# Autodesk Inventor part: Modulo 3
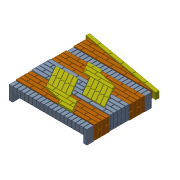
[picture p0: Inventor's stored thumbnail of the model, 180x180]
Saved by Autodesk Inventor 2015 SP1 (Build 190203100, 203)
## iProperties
Created: 2015-04
Part Number: Modulo 3
Material: Generic
Document SubType Name: Modeling
Designer: treina2
Density: 1 g/cm^3
Appearance: Default
Author: treina2
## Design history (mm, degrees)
sketch "Sketch1"
  geometry: L1 (994.875, 828.16)-(1008.247, 805) reference; L2 (1109.875, 329)-(1109.875, 387) reference; L3 (1109.875, 387)-(869.875, 387) reference; L4 (869.875, 387)-(869.875, 329) reference; L5 (340.73, 319)-(244.875, 319) reference; L6 (244.875, 319)-(244.875, 261) reference; L7 (939.842, 183)-(836.807, 183) reference; L8 (939.842, 183)-(744.875, 183) reference; L9 (744.875, 183)-(744.875, 125) reference; L10 (861.322, 319)-(836.807, 319) reference; L11 (739.101, 329)-(859.875, 329) reference; L12 (859.875, 329)-(859.875, 387) reference; L13 (859.875, 387)-(705.615, 387) reference; L14 (1234.875, 941)-(994.875, 941) reference; L15 (994.875, 941)-(994.875, 999) reference; L16 (994.875, 999)-(1234.875, 999) reference; L17 (1234.875, 999)-(1234.875, 941) reference; L18 (619.875, 1134)-(859.875, 1134) reference; L19 (859.875, 1134)-(859.875, 1192) reference; L20 (859.875, 1192)-(619.875, 1192) reference; L21 (619.875, 1192)-(619.875, 1134) reference; L22 (136.5, 0)-(136.5, 115) reference; L23 (136.5, 115)-(194.5, 115) reference; L24 (194.5, 115)-(194.5, 0) reference; L25 (194.5, 0)-(136.5, 0) reference; L26 (859.875, 125)-(973.328, 125) reference; L27 (494.875, 669)-(682.621, 669) reference; L28 (119.875, 465)-(256.437, 465) reference; L29 (301.47, 659)-(234.497, 659) reference; L30 (234.497, 659)-(335.632, 483.83) reference; L31 (335.632, 483.83)-(385.861, 512.83) reference; L32 (385.861, 512.83)-(301.47, 659) reference; L33 (-5.125, 261)-(234.875, 261) reference; L34 (234.875, 261)-(234.875, 319) reference; L35 (234.875, 319)-(-5.125, 319) reference; L36 (-5.125, 319)-(-5.125, 261) reference; L37 (832.83, 329)-(859.875, 329) reference; L38 (859.875, 329)-(859.875, 387) reference; L39 (859.875, 387)-(809.762, 387) reference; L40 (619.875, 193)-(642.243, 193) reference; L41 (340.73, 319)-(244.875, 319) reference; L42 (244.875, 319)-(244.875, 261) reference; L43 (619.875, 197.266)-(619.875, 193) reference; L44 (334.956, 329)-(301.47, 387) reference; L45 (494.875, 261)-(734.875, 261) reference; L46 (244.875, 261)-(369.875, 261) reference; L47 (491.996, 329)-(390.861, 504.17) reference; L48 (744.875, 261)-(849.113, 261) reference; L49 (900.582, 251)-(869.875, 251) reference; L50 (869.875, 251)-(869.875, 193) reference; L51 (385.763, 261)-(352.277, 319) reference; L52 (695.615, 193)-(859.875, 193) reference; L53 (859.875, 193)-(859.875, 251) reference; L54 (859.875, 251)-(619.875, 251) reference; L55 (619.875, 251)-(619.875, 207.447) reference; L56 (945.615, 193)-(1109.875, 193) reference; L57 (1109.875, 193)-(1109.875, 251) reference; L58 (1109.875, 251)-(912.129, 251) reference; L59 (906.355, 261)-(984.875, 261) reference; L60 (984.875, 261)-(984.875, 319) reference; L61 (984.875, 319)-(872.869, 319) reference; L62 (144.431, 659)-(119.875, 659) reference; L63 (119.875, 659)-(119.875, 601) reference; L64 (1234.875, 805)-(1008.247, 805) reference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; 3 further points
  constraints: 1806 end point, 395 horizontal, 258 vertical, 116 point on line, 1005 other
workplane "Work Plane1"
sketch "Sketch2"
  geometry: L1 (0, 1009)-(0, 1124) reference; L2 (0, 1124)-(58, 1124) reference; L3 (58, 1124)-(58, 1009) reference; L4 (58, 1009)-(0, 1009) reference; L5 (0, 0)-(0, 115) reference; L6 (0, 115)-(58, 115) reference; L7 (58, 115)-(58, 0) reference; L8 (58, 0)-(0, 0) reference; L9 (126.25, 1124)-(126.25, 1009) reference; L10 (68.25, 1124)-(126.25, 1124) reference; L11 (68.25, 1009)-(68.25, 1124) reference; L12 (126.25, 1009)-(68.25, 1009) reference; L13 (1354.75, 1124)-(1354.75, 1009) reference; L14 (1296.75, 1124)-(1354.75, 1124) reference; L15 (1296.75, 1009)-(1296.75, 1124) reference; L16 (1354.75, 1009)-(1296.75, 1009) reference; L17 (68.25, 0)-(68.25, 115) reference; L18 (68.25, 115)-(126.25, 115) reference; L19 (126.25, 115)-(126.25, 0) reference; L20 (126.25, 0)-(68.25, 0) reference; L21 (1296.75, 0)-(1296.75, 115) reference; L22 (1296.75, 115)-(1354.75, 115) reference; L23 (1354.75, 115)-(1354.75, 0) reference; L24 (1354.75, 0)-(1296.75, 0) reference; 1 further point
extrude "Extrusion2" new body sketch "Sketch2" distance "d6" = 240; taper "d7" = 0 deg
extrude "Extrusion3" new body sketch "Sketch2" distance "d8" = 240; taper "d9" = 0 deg
extrude "Extrusion4" new body sketch "Sketch2" distance "d10" = 240; taper "d11" = 0 deg
extrude "Extrusion5" new body sketch "Sketch2" distance "d12" = 240; taper "d13" = 0 deg
extrude "Extrusion6" new body sketch "Sketch2" distance "d14" = 115; taper "d15" = 0 deg
extrude "Extrusion7" new body sketch "Sketch2" distance "d16" = 115; taper "d17" = 0 deg
extrude "Extrusion8" new body sketch "Sketch1" distance "d24" = 115; taper "d25" = 0 deg
extrude "Extrusion9" new body sketch "Sketch1" distance "d26" = 240; taper "d27" = 0 deg
extrude "Extrusion10" new body sketch "Sketch1" distance "d28" = 240; taper "d29" = 0 deg
extrude "Extrusion11" new body sketch "Sketch1" distance "d30" = 115; taper "d31" = 0 deg
extrude "Extrusion12" new body sketch "Sketch1" distance "d32" = 115; taper "d33" = 0 deg
extrude "Extrusion13" new body sketch "Sketch1" distance "d34" = 115; taper "d35" = 0 deg
extrude "Extrusion14" new body sketch "Sketch1" distance "d36" = 115; taper "d37" = 0 deg
extrude "Extrusion15" new body sketch "Sketch1" distance "d38" = 115; taper "d39" = 0 deg
extrude "Extrusion16" new body sketch "Sketch1" distance "d40" = 115; taper "d41" = 0 deg
extrude "Extrusion17" new body sketch "Sketch1" distance "d42" = 115; taper "d43" = 0 deg
extrude "Extrusion18" new body sketch "Sketch1" distance "d44" = 115; taper "d45" = 0 deg
extrude "Extrusion19" new body sketch "Sketch1" distance "d46" = 115; taper "d47" = 0 deg
extrude "Extrusion20" new body sketch "Sketch1" distance "d48" = 115; taper "d49" = 0 deg
extrude "Extrusion21" new body sketch "Sketch1" distance "d50" = 115; taper "d51" = 0 deg
extrude "Extrusion22" new body sketch "Sketch1" distance "d52" = 115; taper "d53" = 0 deg
extrude "Extrusion23" new body sketch "Sketch1" distance "d54" = 115; taper "d55" = 0 deg
extrude "Extrusion24" new body sketch "Sketch1" distance "d56" = 115; taper "d57" = 0 deg
extrude "Extrusion25" new body sketch "Sketch1" distance "d58" = 115; taper "d59" = 0 deg
extrude "Extrusion26" new body sketch "Sketch1" distance "d60" = 115; taper "d61" = 0 deg
extrude "Extrusion27" new body sketch "Sketch1" distance "d62" = 115; taper "d63" = 0 deg
extrude "Extrusion28" new body sketch "Sketch1" distance "d64" = 115; taper "d65" = 0 deg
extrude "Extrusion29" new body sketch "Sketch1" distance "d66" = 115; taper "d67" = 0 deg
extrude "Extrusion30" new body sketch "Sketch1" distance "d68" = 115; taper "d69" = 0 deg
extrude "Extrusion31" new body sketch "Sketch1" distance "d70" = 115; taper "d71" = 0 deg
extrude "Extrusion32" new body sketch "Sketch1" distance "d72" = 115; taper "d73" = 0 deg
extrude "Extrusion33" new body sketch "Sketch1" distance "d74" = 115; taper "d75" = 0 deg
extrude "Extrusion34" new body sketch "Sketch1" distance "d76" = 115; taper "d77" = 0 deg
extrude "Extrusion35" new body sketch "Sketch1" distance "d78" = 115; taper "d79" = 0 deg
extrude "Extrusion36" new body sketch "Sketch1" distance "d80" = 115; taper "d81" = 0 deg
extrude "Extrusion37" new body sketch "Sketch1" distance "d82" = 240; taper "d83" = 0 deg
extrude "Extrusion38" new body sketch "Sketch1" distance "d84" = 240; taper "d85" = 0 deg
extrude "Extrusion39" new body sketch "Sketch1" distance "d86" = 240; taper "d87" = 0 deg
extrude "Extrusion40" new body sketch "Sketch1" distance "d88" = 240; taper "d89" = 0 deg
extrude "Extrusion41" new body sketch "Sketch1" distance "d90" = 115; taper "d91" = 0 deg
extrude "Extrusion42" new body sketch "Sketch1" distance "d92" = 115; taper "d93" = 0 deg
extrude "Extrusion43" new body sketch "Sketch1" distance "d94" = 115; taper "d95" = 0 deg
extrude "Extrusion44" new body sketch "Sketch1" distance "d96" = 115; taper "d97" = 0 deg
extrude "Extrusion45" new body sketch "Sketch1" distance "d98" = 115; taper "d99" = 0 deg
extrude "Extrusion46" new body sketch "Sketch1" distance "d100" = 115; taper "d101" = 0 deg
extrude "Extrusion47" new body sketch "Sketch1" distance "d102" = 115; taper "d103" = 0 deg
extrude "Extrusion48" new body sketch "Sketch1" distance "d104" = 115; taper "d105" = 0 deg
extrude "Extrusion49" new body sketch "Sketch1" distance "d106" = 115; taper "d107" = 0 deg
extrude "Extrusion50" new body sketch "Sketch1" distance "d108" = 115; taper "d109" = 0 deg
extrude "Extrusion51" new body sketch "Sketch1" distance "d110" = 115; taper "d111" = 0 deg
extrude "Extrusion52" new body sketch "Sketch1" distance "d112" = 115; taper "d113" = 0 deg
extrude "Extrusion53" new body sketch "Sketch1" distance "d114" = 240; taper "d115" = 0 deg
extrude "Extrusion54" new body sketch "Sketch1" distance "d116" = 240; taper "d117" = 0 deg
extrude "Extrusion68" new body sketch "Sketch1" distance "d144" = 240; taper "d145" = 0 deg
extrude "Extrusion69" new body sketch "Sketch1" distance "d146" = 240; taper "d147" = 0 deg
extrude "Extrusion70" new body sketch "Sketch1" distance "d148" = 115; taper "d149" = 0 deg
extrude "Extrusion71" new body sketch "Sketch1" distance "d150" = 115; taper "d151" = 0 deg
extrude "Extrusion72" new body sketch "Sketch1" distance "d152" = 115; taper "d153" = 0 deg
extrude "Extrusion73" new body sketch "Sketch1" distance "d154" = 115; taper "d155" = 0 deg
extrude "Extrusion74" new body sketch "Sketch1" distance "d156" = 115; taper "d157" = 0 deg
extrude "Extrusion75" new body sketch "Sketch1" distance "d158" = 115; taper "d159" = 0 deg
extrude "Extrusion76" new body sketch "Sketch1" distance "d160" = 115; taper "d161" = 0 deg
extrude "Extrusion77" new body sketch "Sketch1" distance "d162" = 115; taper "d163" = 0 deg
extrude "Extrusion78" new body sketch "Sketch1" distance "d164" = 115; taper "d165" = 0 deg
extrude "Extrusion79" new body sketch "Sketch1" distance "d166" = 115; taper "d167" = 0 deg
workplane "Work Plane2"
sketch "Sketch3"
  geometry: L1 (-5.125, 669)-(234.875, 669) reference; L2 (234.875, 727)-(-5.125, 727) reference; L3 (-5.125, 727)-(-5.125, 669) reference; L4 (234.875, 669)-(234.875, 727) reference; L5 (244.875, 727)-(244.875, 669) reference; L6 (392.943, 727)-(244.875, 727) reference; L7 (244.875, 669)-(369.875, 669) reference; L8 (380.637, 669)-(682.621, 669) reference; L9 (484.875, 727)-(244.875, 727) reference; L10 (484.875, 669)-(484.875, 727) reference; L11 (494.875, 727)-(494.875, 669) reference; L12 (649.135, 727)-(494.875, 727) reference; L13 (244.875, 669)-(484.875, 669) reference; L14 (682.621, 669)-(649.135, 727) reference; L15 (582.062, 601)-(609.875, 601) reference; L16 (609.875, 601)-(609.875, 659) reference; L17 (609.875, 659)-(548.576, 659) reference; L18 (548.576, 659)-(582.062, 601) reference; L19 (619.875, 659)-(619.875, 601) reference; L20 (688.395, 659)-(619.875, 659) reference; L21 (721.881, 601)-(688.395, 659) reference; L22 (619.875, 601)-(721.881, 601) reference; L23 (727.654, 591)-(587.836, 591) reference; L24 (734.875, 578.494)-(727.654, 591) reference; L25 (734.875, 533)-(734.875, 578.494) reference; L26 (621.322, 533)-(734.875, 533) reference; L27 (621.322, 533)-(587.836, 591) reference; L28 (660.582, 465)-(627.096, 523) reference; L29 (766.914, 523)-(627.096, 523) reference; L30 (800.401, 465)-(766.914, 523) reference; L31 (660.582, 465)-(800.401, 465) reference; L32 (744.875, 533)-(761.141, 533) reference; L33 (744.875, 561.173)-(744.875, 533) reference; L34 (761.141, 533)-(744.875, 561.173) reference; L35 (699.842, 397)-(734.875, 397) reference; L36 (734.875, 397)-(734.875, 455) reference; L37 (699.842, 397)-(666.355, 455) reference; L38 (734.875, 455)-(666.355, 455) reference; L39 (744.875, 455)-(744.875, 397) reference; L40 (984.875, 455)-(744.875, 455) reference; L41 (744.875, 397)-(849.113, 397) reference; L42 (859.875, 397)-(984.875, 397) reference; L43 (984.875, 397)-(984.875, 455) reference; L44 (744.875, 397)-(984.875, 397) reference; L45 (994.875, 455)-(1234.875, 455) reference; L46 (994.875, 397)-(994.875, 455) reference; L47 (1234.875, 397)-(994.875, 397) reference; L48 (1234.875, 455)-(1234.875, 397) reference; L49 (1359.875, 455)-(1244.875, 455) reference; L50 (1244.875, 455)-(1244.875, 397) reference; L51 (1244.875, 397)-(1359.875, 397) reference; L52 (1359.875, 397)-(1359.875, 455) reference; L53 (1359.875, 465)-(1204.546, 465) reference; L54 (1359.875, 523)-(1359.875, 465) reference; L55 (1171.059, 523)-(1359.875, 523) reference; L56 (1171.059, 523)-(1204.546, 465) reference; L57 (1234.875, 533)-(1165.286, 533) reference; L58 (1234.875, 591)-(1234.875, 533) reference; L59 (1131.8, 591)-(1234.875, 591) reference; L60 (1131.8, 591)-(1165.286, 533) reference; L61 (1359.875, 601)-(1126.026, 601) reference; L62 (1119.875, 611.654)-(1126.026, 601) reference; L63 (1119.875, 611.654)-(1119.875, 659) reference; L64 (1109.875, 628.975)-(1109.875, 659) reference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; 1 further point
extrude "Extrusion80" new body sketch "Sketch3" distance "d169" = 115; taper "d170" = 0 deg
extrude "Extrusion81" new body sketch "Sketch3" distance "d171" = 115; taper "d172" = 0 deg
extrude "Extrusion82" new body sketch "Sketch3" distance "d173" = 115; taper "d174" = 0 deg
extrude "Extrusion83" new body sketch "Sketch3" distance "d175" = 115; taper "d176" = 0 deg
extrude "Extrusion84" new body sketch "Sketch3" distance "d177" = 115; taper "d178" = 0 deg
extrude "Extrusion85" new body sketch "Sketch3" distance "d179" = 115; taper "d180" = 0 deg
extrude "Extrusion86" new body sketch "Sketch3" distance "d181" = 115; taper "d182" = 0 deg
extrude "Extrusion87" new body sketch "Sketch3" distance "d183" = 115; taper "d184" = 0 deg
extrude "Extrusion88" new body sketch "Sketch3" distance "d185" = 115; taper "d186" = 0 deg
extrude "Extrusion89" new body sketch "Sketch3" distance "d187" = 115; taper "d188" = 0 deg
extrude "Extrusion90" new body sketch "Sketch3" distance "d189" = 115; taper "d190" = 0 deg
extrude "Extrusion91" new body sketch "Sketch3" distance "d191" = 115; taper "d192" = 0 deg
extrude "Extrusion92" new body sketch "Sketch3" distance "d193" = 115; taper "d194" = 0 deg
extrude "Extrusion93" new body sketch "Sketch3" distance "d195" = 115; taper "d196" = 0 deg
extrude "Extrusion94" new body sketch "Sketch3" distance "d197" = 115; taper "d198" = 0 deg
extrude "Extrusion95" new body sketch "Sketch3" distance "d199" = 115; taper "d200" = 0 deg
extrude "Extrusion96" new body sketch "Sketch3" distance "d201" = 115; taper "d202" = 0 deg
extrude "Extrusion97" new body sketch "Sketch3" distance "d203" = 115; taper "d204" = 0 deg
extrude "Extrusion98" new body sketch "Sketch3" distance "d205" = 115; taper "d206" = 0 deg
extrude "Extrusion99" new body sketch "Sketch3" distance "d207" = 115; taper "d208" = 0 deg
extrude "Extrusion100" new body sketch "Sketch3" distance "d209" = 115; taper "d210" = 0 deg
extrude "Extrusion101" new body sketch "Sketch3" distance "d211" = 240; taper "d212" = 0 deg
extrude "Extrusion102" new body sketch "Sketch3" distance "d213" = 240; taper "d214" = 0 deg
extrude "Extrusion103" new body sketch "Sketch3" distance "d215" = 240; taper "d216" = 0 deg
extrude "Extrusion104" new body sketch "Sketch3" distance "d217" = 240; taper "d218" = 0 deg
extrude "Extrusion105" new body sketch "Sketch3" distance "d219" = 240; taper "d220" = 0 deg
workplane "Work Plane3"
sketch "Sketch4"
  geometry: L1 (-46.235, 1450.984)-(190.119, 1409.309) reference; L2 (190.119, 1409.309)-(180.047, 1352.19) reference; L3 (-56.307, 1393.865)-(-46.235, 1450.984) reference; L4 (180.047, 1352.19)-(-56.307, 1393.865) reference; L5 (199.967, 1407.572)-(436.321, 1365.897) reference; L6 (189.895, 1350.453)-(199.967, 1407.572) reference; L7 (436.321, 1365.897)-(426.249, 1308.778) reference; L8 (436.097, 1307.041)-(446.169, 1364.16) reference; L9 (446.169, 1364.16)-(682.523, 1322.485) reference; L10 (682.299, 1263.629)-(692.371, 1320.748) reference; L11 (692.371, 1320.748)-(928.724, 1279.072) reference; L12 (682.523, 1322.485)-(672.451, 1265.366) reference; L13 (928.501, 1220.217)-(938.573, 1277.336) reference; L14 (928.724, 1279.072)-(918.653, 1221.954) reference; L15 (938.573, 1277.336)-(1174.926, 1235.66) reference; L16 (1174.703, 1176.805)-(1184.775, 1233.924) reference; L17 (1174.926, 1235.66)-(1164.855, 1178.542) reference; L18 (1184.775, 1233.924)-(1421.128, 1192.248) reference; L19 (1411.057, 1135.13)-(1174.703, 1176.805) reference; L20 (1421.128, 1192.248)-(1411.057, 1135.13) reference; 3 further points
  constraints: 1 other
extrude "Extrusion106" new body sketch "Sketch4" distance "d222" = 115; taper "d223" = 0 deg
extrude "Extrusion107" new body sketch "Sketch4" distance "d224" = 115; taper "d225" = 0 deg
extrude "Extrusion108" new body sketch "Sketch4" distance "d226" = 115; taper "d227" = 0 deg
extrude "Extrusion109" new body sketch "Sketch4" distance "d228" = 115; taper "d229" = 0 deg
extrude "Extrusion110" new body sketch "Sketch4" distance "d230" = 115; taper "d231" = 0 deg
extrude "Extrusion111" new body sketch "Sketch4" distance "d232" = 115; taper "d233" = 0 deg
workplane "Work Plane4"
sketch "Sketch5"
  geometry: L1 (994.875, 828.16)-(1008.247, 805) reference; L2 (1109.875, 329)-(1109.875, 387) reference; L3 (1109.875, 387)-(869.875, 387) reference; L4 (869.875, 387)-(869.875, 329) reference; L5 (340.73, 319)-(244.875, 319) reference; L6 (244.875, 319)-(244.875, 261) reference; L7 (939.842, 183)-(836.807, 183) reference; L8 (939.842, 183)-(744.875, 183) reference; L9 (744.875, 183)-(744.875, 125) reference; L10 (861.322, 319)-(836.807, 319) reference; L11 (739.101, 329)-(859.875, 329) reference; L12 (859.875, 329)-(859.875, 387) reference; L13 (859.875, 387)-(705.615, 387) reference; L14 (1234.875, 941)-(994.875, 941) reference; L15 (994.875, 941)-(994.875, 999) reference; L16 (994.875, 999)-(1234.875, 999) reference; L17 (1234.875, 999)-(1234.875, 941) reference; L18 (619.875, 1134)-(859.875, 1134) reference; L19 (859.875, 1134)-(859.875, 1192) reference; L20 (859.875, 1192)-(619.875, 1192) reference; L21 (619.875, 1192)-(619.875, 1134) reference; L22 (136.5, 0)-(136.5, 115) reference; L23 (136.5, 115)-(194.5, 115) reference; L24 (194.5, 115)-(194.5, 0) reference; L25 (194.5, 0)-(136.5, 0) reference; L26 (859.875, 125)-(973.328, 125) reference; L27 (494.875, 669)-(682.621, 669) reference; L28 (119.875, 465)-(256.437, 465) reference; L29 (301.47, 659)-(234.497, 659) reference; L30 (234.497, 659)-(335.632, 483.83) reference; L31 (335.632, 483.83)-(385.861, 512.83) reference; L32 (385.861, 512.83)-(301.47, 659) reference; L33 (-5.125, 261)-(234.875, 261) reference; L34 (234.875, 261)-(234.875, 319) reference; L35 (234.875, 319)-(-5.125, 319) reference; L36 (-5.125, 319)-(-5.125, 261) reference; L37 (832.83, 329)-(859.875, 329) reference; L38 (859.875, 329)-(859.875, 387) reference; L39 (859.875, 387)-(809.762, 387) reference; L40 (619.875, 193)-(642.243, 193) reference; L41 (340.73, 319)-(244.875, 319) reference; L42 (244.875, 319)-(244.875, 261) reference; L43 (619.875, 197.266)-(619.875, 193) reference; L44 (334.956, 329)-(301.47, 387) reference; L45 (494.875, 261)-(734.875, 261) reference; L46 (244.875, 261)-(369.875, 261) reference; L47 (491.996, 329)-(390.861, 504.17) reference; L48 (744.875, 261)-(849.113, 261) reference; L49 (900.582, 251)-(869.875, 251) reference; L50 (869.875, 251)-(869.875, 193) reference; L51 (385.763, 261)-(352.277, 319) reference; L52 (695.615, 193)-(859.875, 193) reference; L53 (859.875, 193)-(859.875, 251) reference; L54 (859.875, 251)-(619.875, 251) reference; L55 (619.875, 251)-(619.875, 207.447) reference; L56 (945.615, 193)-(1109.875, 193) reference; L57 (1109.875, 193)-(1109.875, 251) reference; L58 (1109.875, 251)-(912.129, 251) reference; L59 (906.355, 261)-(984.875, 261) reference; L60 (984.875, 261)-(984.875, 319) reference; L61 (984.875, 319)-(872.869, 319) reference; L62 (144.431, 659)-(119.875, 659) reference; L63 (119.875, 659)-(119.875, 601) reference; L64 (1234.875, 805)-(1008.247, 805) reference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; 4 further points
  constraints: 1806 end point, 395 horizontal, 258 vertical, 116 point on line, 1005 other
extrude "Extrusion112" new body sketch "Sketch5" distance "d235" = 115; taper "d236" = 0 deg
extrude "Extrusion113" new body sketch "Sketch5" distance "d237" = 115; taper "d238" = 0 deg
extrude "Extrusion114" new body sketch "Sketch5" distance "d239" = 115; taper "d240" = 0 deg
extrude "Extrusion115" new body sketch "Sketch5" distance "d241" = 115; taper "d242" = 0 deg
extrude "Extrusion116" new body sketch "Sketch5" distance "d243" = 115; taper "d244" = 0 deg
extrude "Extrusion117" new body sketch "Sketch5" distance "d245" = 115; taper "d246" = 0 deg
extrude "Extrusion118" new body sketch "Sketch5" distance "d247" = 115; taper "d248" = 0 deg
extrude "Extrusion119" new body sketch "Sketch5" distance "d249" = 115; taper "d250" = 0 deg
extrude "Extrusion120" new body sketch "Sketch5" distance "d251" = 115; taper "d252" = 0 deg
extrude "Extrusion121" new body sketch "Sketch5" distance "d253" = 115; taper "d254" = 0 deg
extrude "Extrusion122" new body sketch "Sketch5" distance "d255" = 115; taper "d256" = 0 deg
extrude "Extrusion123" new body sketch "Sketch5" distance "d257" = 115; taper "d258" = 0 deg
extrude "Extrusion124" new body sketch "Sketch5" distance "d259" = 115; taper "d260" = 0 deg
extrude "Extrusion125" new body sketch "Sketch5" distance "d261" = 115; taper "d262" = 0 deg
extrude "Extrusion126" new body sketch "Sketch5" distance "d263" = 115; taper "d264" = 0 deg
extrude "Extrusion127" new body sketch "Sketch5" distance "d265" = 115; taper "d266" = 0 deg
extrude "Extrusion128" new body sketch "Sketch5" distance "d267" = 115; taper "d268" = 0 deg
extrude "Extrusion129" new body sketch "Sketch5" distance "d269" = 115; taper "d270" = 0 deg
extrude "Extrusion130" new body sketch "Sketch5" distance "d271" = 115; taper "d272" = 0 deg
extrude "Extrusion131" new body sketch "Sketch5" distance "d273" = 115; taper "d274" = 0 deg
extrude "Extrusion132" new body sketch "Sketch5" distance "d275" = 115; taper "d276" = 0 deg
extrude "Extrusion133" new body sketch "Sketch5" distance "d277" = 115; taper "d278" = 0 deg
extrude "Extrusion134" new body sketch "Sketch5" distance "d279" = 115; taper "d280" = 0 deg
extrude "Extrusion135" new body sketch "Sketch5" distance "d281" = 115; taper "d282" = 0 deg
extrude "Extrusion136" new body sketch "Sketch5" distance "d283" = 115; taper "d284" = 0 deg
extrude "Extrusion137" new body sketch "Sketch5" distance "d285" = 115; taper "d286" = 0 deg
extrude "Extrusion138" new body sketch "Sketch5" distance "d287" = 115; taper "d288" = 0 deg
extrude "Extrusion139" new body sketch "Sketch5" distance "d289" = 115; taper "d290" = 0 deg
extrude "Extrusion140" new body sketch "Sketch5" distance "d291" = 115; taper "d292" = 0 deg
extrude "Extrusion141" new body sketch "Sketch5" distance "d293" = 115; taper "d294" = 0 deg
extrude "Extrusion142" new body sketch "Sketch5" distance "d295" = 115; taper "d296" = 0 deg
extrude "Extrusion143" new body sketch "Sketch5" distance "d297" = 115; taper "d298" = 0 deg
extrude "Extrusion144" new body sketch "Sketch5" distance "d299" = 115; taper "d300" = 0 deg
extrude "Extrusion145" new body sketch "Sketch5" distance "d301" = 115; taper "d302" = 0 deg
extrude "Extrusion146" new body sketch "Sketch5" distance "d303" = 115; taper "d304" = 0 deg
extrude "Extrusion147" new body sketch "Sketch5" distance "d305" = 115; taper "d306" = 0 deg
workplane "Work Plane5"
sketch "Sketch6"
  geometry: L1 (-1119.875, 931)-(-1359.875, 931) reference; L2 (-1359.875, 873)-(-1244.875, 873); L3 (-1244.875, 873)-(-1244.875, 931); L4 (-1244.875, 931)-(-1359.875, 931); L5 (-1359.875, 931)-(-1359.875, 873); 1 further point
  constraints: 8 end point, 2 parallel, 1 horizontal, 1 perpendicular, 1 point on line
  dimensions: "d308" = 115 distance between parallel lines of L5 L3
extrude "Extrusion148" new body sketch "Sketch6" stored distance "d309" = 115; taper "d310" = 0 deg
pattern_linear "Rectangular Pattern5" dims "d316" = 136
workplane "Work Plane6"
sketch "Sketch7"
  geometry: L1 (-1119.875, 659)-(-1359.875, 659) reference; L2 (-1359.875, 601)-(-1244.875, 601); L3 (-1244.875, 601)-(-1244.875, 659); L4 (-1244.875, 659)-(-1359.875, 659); L5 (-1359.875, 659)-(-1359.875, 601); 1 further point
  constraints: 8 end point, 2 parallel, 1 horizontal, 1 perpendicular, 1 point on line
  dimensions: "d318" = 115 distance between parallel lines of L5 L3
extrude "Extrusion149" new body sketch "Sketch7" distance "d319" = 115; taper "d320" = 0 deg
pattern_linear "Rectangular Pattern6" dims "d323" = 136
workplane "Work Plane7"
sketch "Sketch8"
  geometry: L1 (-1119.875, 387)-(-1359.875, 387) reference; L2 (-1359.875, 329)-(-1244.875, 329); L3 (-1244.875, 329)-(-1244.875, 387); L4 (-1244.875, 387)-(-1359.875, 387); L5 (-1359.875, 387)-(-1359.875, 329); 1 further point
  constraints: 8 end point, 2 parallel, 1 horizontal, 1 perpendicular, 1 point on line
  dimensions: "d325" = 115 distance between parallel lines of L5 L3
extrude "Extrusion150" new body sketch "Sketch8" distance "d326" = 115; taper "d327" = 0 deg
pattern_linear "Rectangular Pattern7" dims "d330" = 136
workplane "Work Plane8"
sketch "Sketch9"
  geometry: L1 (-234.875, 1202)-(5.125, 1202) reference; L2 (5.125, 1260)-(-109.875, 1260); L3 (-109.875, 1260)-(-109.875, 1202); L4 (-109.875, 1202)-(5.125, 1202); L5 (5.125, 1202)-(5.125, 1260); 1 further point
  constraints: 8 end point, 2 parallel, 1 horizontal, 1 perpendicular, 1 point on line
  dimensions: "d332" = 115 distance between parallel lines of L5 L3
extrude "Extrusion151" new body sketch "Sketch9" distance "d333" = 115; taper "d334" = 0 deg
workplane "Work Plane9"
sketch "Sketch10"
  geometry: L1 (-234.875, 941)-(5.125, 941) reference; L2 (5.125, 999)-(-109.875, 999); L3 (-109.875, 999)-(-109.875, 941); L4 (-109.875, 941)-(5.125, 941); L5 (5.125, 941)-(5.125, 999); 1 further point
  constraints: 8 end point, 2 parallel, 1 horizontal, 1 perpendicular, 1 point on line
  dimensions: "d336" = 115 distance between parallel lines of L5 L3
extrude "Extrusion152" new body sketch "Sketch10" distance "d337" = 115; taper "d338" = 0 deg
pattern_linear "Rectangular Pattern8" dims "d341" = 136
workplane "Work Plane10"
sketch "Sketch11"
  geometry: L1 (-234.875, 669)-(5.125, 669) reference; L2 (5.125, 727)-(-109.875, 727); L3 (-109.875, 727)-(-109.875, 669); L4 (-109.875, 669)-(5.125, 669); L5 (5.125, 669)-(5.125, 727); 1 further point
  constraints: 8 end point, 2 parallel, 1 horizontal, 1 perpendicular, 1 point on line
  dimensions: "d343" = 115 distance between parallel lines of L5 L3
extrude "Extrusion153" new body sketch "Sketch11" distance "d344" = 115; taper "d345" = 0 deg
pattern_linear "Rectangular Pattern9" dims "d348" = 136
workplane "Work Plane11"
sketch "Sketch12"
  geometry: L1 (5.125, 319)-(-109.875, 319); L2 (-109.875, 319)-(-109.875, 261); L3 (-109.875, 261)-(5.125, 261); L4 (5.125, 261)-(5.125, 319); 1 further point
  constraints: 8 end point, 2 parallel, 1 horizontal, 1 perpendicular
  dimensions: "d350" = 115 distance between parallel lines of L4 L2
extrude "Extrusion154" new body sketch "Sketch12" distance "d351" = 115; taper "d352" = 0 deg
pattern_linear "Rectangular Pattern10" dims "d355" = 136
workplane "Work Plane12"
sketch "Sketch14"
  geometry: L1 (-109.875, 1338)-(-109.875, 1354.409); L2 (5.125, 1338)-(-109.875, 1338); L3 (-202.934, 1338)-(5.125, 1338) reference; L4 (5.125, 1374.686)-(-109.875, 1354.409); L5 (5.125, 1374.686)-(-202.934, 1338) reference; L6 (5.125, 1338)-(5.125, 1374.686); L7 (5.125, 1338)-(5.125, 1374.686) reference; 2 further points
  constraints: 8 end point, 2 point on line, 1 collinear, 1 vertical
extrude "Extrusion155" new body sketch "Sketch14" distance "d357" = 115; taper "d358" = 0 deg
workplane "Work Plane13"
sketch "Sketch15"
  geometry: L1 (621.422, 795)-(811.948, 465); L2 (722.556, 619.83)-(621.422, 795) reference; L3 (811.948, 465)-(1192.999, 465); L4 (1192.999, 465)-(1126.026, 465) reference; L5 (1192.999, 465)-(957.44, 873); L6 (957.44, 873)-(653.361, 931); L7 (653.361, 931)-(859.875, 891.61) reference; L8 (653.361, 931)-(614.101, 999); L9 (614.101, 999)-(375.649, 999); L10 (375.649, 999)-(484.875, 999) reference; L11 (375.649, 999)-(487.654, 805); L12 (409.135, 941)-(375.649, 999) reference; L13 (621.422, 795)-(615.649, 805); L14 (734.875, 805)-(494.875, 805) reference; L15 (615.649, 805)-(487.654, 805); L16 (646.99, 922.035)-(951.069, 864.035); L17 (951.069, 864.035)-(1175.678, 475); L18 (1175.678, 475)-(817.721, 475); L19 (817.721, 475)-(630.082, 800); L20 (630.082, 800)-(621.422, 815); L21 (621.422, 815)-(493.428, 815); L22 (493.428, 815)-(392.969, 989); L23 (392.969, 989)-(608.328, 989); L24 (608.328, 989)-(646.99, 922.035); L25 (155.978, 659)-(537.029, 659); L26 (537.029, 659)-(733.328, 319); L27 (626.42, 504.17)-(727.554, 329) reference; L28 (733.328, 319)-(859.875, 319); L29 (859.875, 319)-(971.881, 125); L30 (971.881, 125)-(734.615, 125); L31 (973.328, 125)-(744.875, 125) reference; L32 (734.615, 125)-(695.323, 193.056); L33 (695.323, 193.056)-(391.537, 251); L34 (609.875, 209.354)-(391.537, 251) reference; L35 (391.537, 251)-(155.978, 659); L36 (531.255, 649)-(173.298, 649); L37 (173.298, 649)-(397.908, 259.965); L38 (397.908, 259.965)-(701.694, 202.021); L39 (701.694, 202.021)-(740.388, 135); L40 (740.388, 135)-(954.56, 135); L41 (954.56, 135)-(854.101, 309); L42 (854.101, 309)-(727.554, 309); L43 (727.554, 309)-(531.255, 649); 1 further point
  constraints: 68 end point, 12 parallel, 8 collinear, 1 horizontal, 1 point on line, 15 other
  dimensions: "d360" = 10 distance between parallel lines of L6 L16; "d361" = 10 distance between parallel lines of L25 L36
extrude "Extrusion156" new body sketch "Sketch15" distance "d362" = 95; taper "d363" = 0 deg
workplane "Work Plane14"
sketch "Sketch16"
  geometry: L1 (646.99, 922.035)-(951.069, 864.035) reference; L2 (608.328, 989)-(646.99, 922.035) reference; L3 (392.969, 989)-(608.328, 989) reference; L4 (493.428, 815)-(392.969, 989) reference; L5 (621.422, 815)-(493.428, 815) reference; L6 (817.721, 475)-(621.422, 815) reference; L7 (1175.678, 475)-(817.721, 475) reference; L8 (951.069, 864.035)-(1175.678, 475) reference; L9 (531.255, 649)-(173.298, 649) reference; L10 (173.298, 649)-(397.908, 259.965) reference; L11 (397.908, 259.965)-(701.694, 202.021) reference; L12 (701.694, 202.021)-(740.388, 135) reference; L13 (740.388, 135)-(954.56, 135) reference; L14 (954.56, 135)-(854.101, 309) reference; L15 (854.101, 309)-(727.554, 309) reference; L16 (727.554, 309)-(531.255, 649) reference; L17 (1354.75, 0)-(1296.75, 0) reference; L18 (1344.75, 0)-(10, 0); L19 (58, 0)-(0, 0) reference; L20 (1344.75, 0)-(1344.75, 1195.562); L21 (10, 0)-(10, 1430.914); L22 (-46.235, 1450.984)-(190.119, 1409.309) reference; L23 (1184.775, 1233.924)-(1421.128, 1192.248) reference; L24 (10, 1430.914)-(1344.75, 1195.562); 2 further points
  constraints: 8 end point, 4 point on line, 2 vertical, 1 parallel
  dimensions: "d367" = 10 distance from line of L17.start L20; "d368" = 10 distance from line of L19.end L21 (= d367); "d370" = 10 distance between parallel lines of L24 L22
extrude "Extrusion157" join sketch "Sketch16" distance "d365" = 95; taper "d366" = 0 deg
sketch "Sketch17"
  geometry: L1 (1490.517, 397)-(1490.517, -135.871); L2 (1490.517, -135.871)-(-86.242, -135.871); L3 (-86.242, -135.871)-(-86.242, 397); L4 (-5.125, 397)-(234.875, 397) reference; L5 (-56.307, 1393.865)-(180.047, 1352.19) reference; L6 (531.255, 649)-(173.298, 649) reference; L7 (173.298, 649)-(397.908, 259.965) reference; L8 (397.908, 259.965)-(701.694, 202.021) reference; L9 (701.694, 202.021)-(740.388, 135) reference; L10 (740.388, 135)-(954.56, 135) reference; L11 (954.56, 135)-(854.101, 309) reference; L12 (854.101, 309)-(727.554, 309) reference; L13 (727.554, 309)-(531.255, 649) reference; L14 (646.99, 922.035)-(951.069, 864.035) reference; L15 (608.328, 989)-(646.99, 922.035) reference; L16 (392.969, 989)-(608.328, 989) reference; L17 (493.428, 815)-(392.969, 989) reference; L18 (621.422, 815)-(493.428, 815) reference; L19 (817.721, 475)-(621.422, 815) reference; L20 (1175.678, 475)-(817.721, 475) reference; L21 (951.069, 864.035)-(1175.678, 475) reference; L22 (-86.242, 397)-(318.791, 397); L23 (676.748, 397)-(1490.517, 397); L24 (234.875, 727)-(-5.125, 727) reference; L25 (1174.703, 1176.805)-(1411.057, 1135.13) reference; L26 (1466.859, 727)-(1466.859, 1125.29); L27 (1466.859, 1125.29)-(-78.295, 1397.742); L28 (-78.295, 1397.742)-(-78.295, 727); L29 (-78.295, 727)-(672.229, 727); L30 (1030.186, 727)-(1466.859, 727); 1 further point
  constraints: 20 end point, 5 collinear, 4 horizontal, 4 parallel, 4 perpendicular, 4 point on line
extrude "Extrusion158" cut sketch "Sketch17" distance "d371" = 10; taper "d372" = 0 deg
sketch "Sketch18"
  geometry: L1 (-5.125, 125)-(234.875, 125) reference; L2 (-122.801, -88.829)-(1458.698, -88.829); L3 (1458.698, -88.829)-(1458.698, 125); L4 (1458.698, 125)-(-122.801, 125); L5 (-122.801, 125)-(-122.801, -88.829); L6 (109.875, 1134)-(-5.125, 1134) reference; L7 (234.875, 999)-(-5.125, 999) reference; L8 (-236.658, 1134)-(1551.727, 1134); L9 (1551.727, 1134)-(1551.727, 999); L10 (1551.727, 999)-(-236.658, 999); L11 (-236.658, 999)-(-236.658, 1134); 1 further point
  constraints: 16 end point, 4 parallel, 3 collinear, 2 horizontal, 2 perpendicular
extrude "Extrusion159" cut sketch "Sketch18" distance "d373" = 10; taper "d374" = 0 deg
sketch "Sketch19"
  geometry: L1 (-646.99, 922.035)-(-608.328, 989) reference; L2 (-608.328, 989)-(-392.969, 989) reference; L3 (-392.969, 989)-(-493.428, 815) reference; L4 (-493.428, 815)-(-621.422, 815) reference; L5 (-621.422, 815)-(-817.721, 475) reference; L6 (-817.721, 475)-(-1175.678, 475) reference; L7 (-1175.678, 475)-(-951.069, 864.035) reference; L8 (-951.069, 864.035)-(-646.99, 922.035) reference; L9 (-173.298, 649)-(-397.908, 259.965) reference; L10 (-397.908, 259.965)-(-701.694, 202.021) reference; L11 (-701.694, 202.021)-(-740.388, 135) reference; L12 (-740.388, 135)-(-954.56, 135) reference; L13 (-954.56, 135)-(-854.101, 309) reference; L14 (-854.101, 309)-(-727.554, 309) reference; L15 (-727.554, 309)-(-531.255, 649) reference; L16 (-531.255, 649)-(-173.298, 649) reference; L17 (-1344.75, 0)-(-10, 0) reference; L18 (-10, 0)-(-10, 1430.914) reference; L19 (-10, 1430.914)-(-1344.75, 1195.562) reference; L20 (-1344.75, 1195.562)-(-1344.75, 0) reference; L21 (-666.103, 948.93)-(-625.649, 1019); L22 (-625.649, 1019)-(-341.007, 1019); L23 (-341.007, 1019)-(-476.107, 785); L24 (-476.107, 785)-(-604.101, 785); L25 (-604.101, 785)-(-800.401, 445); L26 (-800.401, 445)-(-1227.64, 445); L27 (-1227.64, 445)-(-970.182, 890.93); L28 (-970.182, 890.93)-(-666.103, 948.93); L29 (-121.337, 679)-(-378.795, 233.07); L30 (-378.795, 233.07)-(-682.581, 175.126); L31 (-682.581, 175.126)-(-723.068, 105); L32 (-723.068, 105)-(-1006.522, 105); L33 (-1006.522, 105)-(-871.422, 339); L34 (-871.422, 339)-(-744.875, 339); L35 (-744.875, 339)-(-548.576, 679); L36 (-548.576, 679)-(-121.337, 679); L37 (-984.875, 845.481)-(-974.76, 863) reference; L38 (-183.691, 591)-(-217.177, 533) reference; 1 further point
  constraints: 32 end point, 14 other
  dimensions: "d377" = 10 distance between parallel lines of L27 L37; "d378" = 10 distance between parallel lines of L29 L38 (= d377)
extrude "Extrusion160" cut sketch "Sketch19" stored distance "d375" = 10; taper "d376" = 0 deg
sketch "Sketch20"
  geometry: L1 (-682.581, 175.126)-(-723.068, 105) reference; L2 (-723.068, 105)-(-1006.522, 105) reference; L3 (-1006.522, 105)-(-871.422, 339) reference; L4 (-871.422, 339)-(-744.875, 339) reference; L5 (-744.875, 339)-(-548.576, 679) reference; L6 (-548.576, 679)-(-121.337, 679) reference; L7 (-121.337, 679)-(-378.795, 233.07) reference; L8 (-378.795, 233.07)-(-682.581, 175.126) reference; L9 (-476.107, 785)-(-604.101, 785) reference; L10 (-604.101, 785)-(-800.401, 445) reference; L11 (-800.401, 445)-(-1227.64, 445) reference; L12 (-1227.64, 445)-(-970.182, 890.93) reference; L13 (-970.182, 890.93)-(-666.103, 948.93) reference; L14 (-666.103, 948.93)-(-625.649, 1019) reference; L15 (-625.649, 1019)-(-341.007, 1019) reference; L16 (-341.007, 1019)-(-476.107, 785) reference; L17 (-1344.75, 0)-(-10, 0) reference; L18 (-10, 0)-(-10, 1430.914) reference; L19 (-10, 1430.914)-(-1344.75, 1195.562) reference; L20 (-1344.75, 1195.562)-(-1344.75, 0) reference; L21 (-1244.875, 737)-(-1359.875, 737) reference; L22 (-1244.875, 387)-(-1359.875, 387) reference; L23 (-10, 747)-(-10, 1361.865); L24 (-10, 1361.865)-(-1344.75, 1126.513); L25 (-1344.75, 1126.513)-(-1344.75, 747); L26 (-369.875, 1308.564)-(-588.581, 1270) reference; L27 (-10, 0)-(-10, 1430.914) reference; L28 (-1344.75, 747)-(-1053.28, 747); L29 (-626.041, 747)-(-10, 747); L30 (-1359.875, 125)-(-1244.875, 125) reference; L31 (-10, 377)-(-10, 135); L32 (-1344.75, 135)-(-1344.75, 377); L33 (-1344.75, 1195.562)-(-1344.75, 0) reference; L34 (-1344.75, 377)-(-722.936, 377); L35 (-295.696, 377)-(-10, 377); L36 (-10, 135)-(-705.747, 135); L37 (-989.201, 135)-(-1344.75, 135); 1 further point
  constraints: 22 end point, 6 parallel, 6 point on line, 4 collinear, 4 horizontal, 4 perpendicular, 1 vertical
  dimensions: "d379" = 10 distance between parallel lines of L26 L24
extrude "Extrusion161" join sketch "Sketch20" distance "d383" = 10; taper "d384" = 0 deg
sketch "Sketch21"
  geometry: L1 (-1344.75, 0)-(-10, 0); L2 (-10, 0)-(-10, 105); L3 (-10, 105)-(-1344.75, 105); L4 (-1344.75, 105)-(-1344.75, 0); L5 (-1344.75, 135)-(-1344.75, 0) reference; L6 (-1344.75, 0)-(-10, 0) reference; L7 (-10, 0)-(-10, 135) reference; L8 (0, 115)-(-58, 115) reference; L9 (-1344.75, 1114)-(-10, 1114); L10 (-10, 1114)-(-10, 1019); L11 (-10, 1019)-(-1344.75, 1019); L12 (-1344.75, 1019)-(-1344.75, 1114); L13 (-1296.75, 1124)-(-1354.75, 1124) reference; L14 (-1354.75, 1009)-(-1296.75, 1009) reference; 1 further point
  constraints: 16 end point, 4 parallel, 3 collinear, 2 horizontal, 2 perpendicular
  dimensions: "d385" = 10 distance between parallel lines of L8 L3; "d386" = 10 distance between parallel lines of L13 L9; "d387" = 10 distance between parallel lines of L14 L11 (= d386)
extrude "Extrusion162" join sketch "Sketch21" distance "d388" = 10; taper "d389" = 0 deg
sketch "Sketch22"
  geometry: L1 (-1344.75, 1126.513)-(-1344.75, 747) reference; L2 (-10, 747)-(-10, 1361.865) reference; L3 (-1344.75, 1114)-(-10, 1114); L4 (-10, 1114)-(-10, 1019); L5 (-10, 1019)-(-1344.75, 1019); L6 (-1344.75, 1019)-(-1344.75, 1114); L7 (-1296.75, 1124)-(-1354.75, 1124) reference; L8 (-1354.75, 1009)-(-1296.75, 1009) reference; 1 further point
  constraints: 8 end point, 2 parallel, 2 point on line, 1 horizontal, 1 perpendicular
  dimensions: "d390" = 10 distance between parallel lines of L7 L3; "d391" = 10 distance between parallel lines of L5 L8 (= d390)
extrude "Extrusion163" join sketch "Sketch22" distance "d392" = 10; taper "d393" = 0 deg
workplane "Work Plane15"
sketch "Sketch24"
  geometry: L1 (-10, 1134)-(-10, 1382.174) reference; L2 (-99.875, 115)-(-10, 115); L3 (-10, 115)-(-10, 1335.791); L4 (-10, 1335.791)-(-99.875, 1335.791); L5 (-99.875, 1335.791)-(-99.875, 115); L6 (-109.875, 591)-(-109.875, 533) reference; L7 (-58, 115)-(0, 115) reference; 1 further point
  constraints: 8 end point, 2 parallel, 1 collinear, 1 horizontal, 1 perpendicular, 1 point on line
  dimensions: "d395" = 10 distance between parallel lines of L6 L5
extrude "Extrusion164" join sketch "Sketch24" stored distance "d396" = 10; taper "d397" = 0 deg
sketch "Sketch25"
  geometry: L1 (-10, 115)-(-10, 1335.791) reference; L2 (-1344.75, 999)-(-10, 999) reference; L3 (-10, 1134.492)-(-103.762, 1134.492); L4 (-103.762, 1134.492)-(-103.762, 999); L5 (-103.762, 999)-(-10, 999); L6 (-10, 999)-(-10, 1134.492); L7 (-111.075, 738.325)-(0, 738.325); L8 (0, 738.325)-(0, 385.009); L9 (0, 385.009)-(-111.075, 385.009); L10 (-111.075, 385.009)-(-111.075, 738.325); 1 further point
  constraints: 16 end point, 4 parallel, 2 horizontal, 2 perpendicular, 2 point on line
extrude "Extrusion165" cut sketch "Sketch25" distance "d398" = 10; taper "d399" = 0 deg
sketch "Sketch26"
  geometry: L1 (-99.875, 1134.492)-(-10, 1134.492) reference; L2 (-1344.75, 999)-(-10, 999) reference; L3 (-48, 1134.492)-(-115.509, 1134.492); L4 (-115.509, 1134.492)-(-115.509, 999); L5 (-115.509, 999)-(-48, 999); L6 (-48, 999)-(-48, 1134.492); L7 (-58, 1124)-(-58, 1009) reference; 1 further point
  constraints: 8 end point, 2 parallel, 2 point on line, 1 horizontal, 1 perpendicular
  dimensions: "d400" = 10 distance between parallel lines of L6 L7
extrude "Extrusion166" cut sketch "Sketch26" stored distance "d401" = 10; taper "d402" = 0 deg
sketch "Sketch27"
  geometry: L1 (-10, 125)-(-1344.75, 125) reference; L2 (-48, 107.309)-(-105.202, 107.309); L3 (-105.202, 107.309)-(-105.202, 125); L4 (-105.202, 125)-(-48, 125); L5 (-48, 125)-(-48, 107.309); L6 (-58, 0)-(-58, 115) reference; 1 further point
  constraints: 8 end point, 2 parallel, 1 horizontal, 1 perpendicular, 1 point on line
  dimensions: "d405" = 10 distance between parallel lines of L6 L5
extrude "Extrusion167" cut sketch "Sketch27" stored distance "d403" = 10; taper "d404" = 0 deg
sketch "Sketch28"
  geometry: L1 (-1354.75, 1009)-(-1296.75, 1009) reference; L2 (-1254.875, 115)-(-1344.75, 115); L3 (-1344.75, 115)-(-1344.75, 1009); L4 (-1344.75, 1009)-(-1254.875, 1009); L5 (-1254.875, 1009)-(-1254.875, 115); L6 (-1244.875, 125)-(-1244.875, 183) reference; L7 (-1296.75, 115)-(-1354.75, 115) reference; L8 (-1344.75, 747)-(-1344.75, 377) reference; 1 further point
  constraints: 8 end point, 2 collinear, 2 parallel, 1 horizontal, 1 perpendicular, 1 point on line
  dimensions: "d406" = 10 distance between parallel lines of L6 L5
extrude "Extrusion168" join sketch "Sketch28" stored distance "d407" = 0; taper "d408" = 0 deg
sketch "Sketch29"
  geometry: L1 (-1344.75, 377)-(-1344.75, 747) reference; L2 (-1254.875, 747)-(-1254.875, 377) reference; L3 (-1344.75, 737)-(-1254.875, 737); L4 (-1254.875, 737)-(-1254.875, 387); L5 (-1254.875, 387)-(-1344.75, 387); L6 (-1344.75, 387)-(-1344.75, 737); L7 (-1244.875, 737)-(-1359.875, 737) reference; L8 (-1244.875, 387)-(-1359.875, 387) reference; 1 further point
  constraints: 8 end point, 2 collinear, 2 parallel, 2 point on line, 1 horizontal, 1 perpendicular
extrude "Extrusion169" cut sketch "Sketch29" distance "d409" = 10; taper "d410" = 0 deg
sketch "Sketch30"
  geometry: L1 (-10, 125)-(-1344.75, 125) reference; L2 (-1306.75, 125)-(-1244.759, 125); L3 (-1244.759, 125)-(-1244.759, 91.405); L4 (-1244.759, 91.405)-(-1306.75, 91.405); L5 (-1306.75, 91.405)-(-1306.75, 125); L6 (-1296.75, 0)-(-1296.75, 115) reference; 1 further point
  constraints: 8 end point, 2 parallel, 1 horizontal, 1 perpendicular, 1 point on line
  dimensions: "d411" = 10 distance between parallel lines of L6 L5
extrude "Extrusion170" cut sketch "Sketch30" stored distance "d412" = 10; taper "d413" = 0 deg
sketch "Sketch31"
  geometry: L1 (-1306.75, 999)-(-1216.7, 999); L2 (-1216.7, 999)-(-1216.7, 1043.154); L3 (-1216.7, 1043.154)-(-1306.75, 1043.154); L4 (-1306.75, 1043.154)-(-1306.75, 999); L5 (-1244.875, 999)-(-1359.875, 999) reference; L6 (-1296.75, 1009)-(-1296.75, 1124) reference; 1 further point
  constraints: 8 end point, 2 parallel, 1 collinear, 1 horizontal, 1 perpendicular
  dimensions: "d414" = 10 distance between parallel lines of L6 L4
extrude "Extrusion171" cut sketch "Sketch31" stored distance "d415" = 10; taper "d416" = 0 deg
combine "Combine1"
node "M3.21"
pattern_linear "Rectangular Pattern2" dims "d20" = 68.25
pattern_linear "Rectangular Pattern3" dims "d23" = 68.25
node "M3.22"
node "M3.23"
node "M3.24"
node "M3.25"
node "M3.26"
feature "Pattern of M3.26:20"
node "M3.27"
feature "Pattern of M3.26:21"
node "M3.28"
feature "Pattern of M3.26:22"
node "M3.29"
feature "Pattern of M3.26:23"
node "M3.30"
feature "Pattern of M3.26:24"
node "M3.31"
feature "Pattern of M3.26:25"
node "M3.32"
feature "Pattern of M3.26:26"
node "M3.33"
feature "Pattern of M3.26:27"
node "M3.34"
feature "Pattern of M3.26:28"
node "M3.35"
feature "Pattern of M3.26:29"
node "M3.36"
feature "Pattern of M3.26:30"
node "M3.37"
feature "Pattern of M3.26:31"
node "M3.38"
feature "Pattern of M3.26:32"
node "M3.39"
feature "Pattern of M3.26:33"
node "M3.40"
feature "Pattern of M3.26:34"
node "M3.41"
feature "Pattern of M3.26:35"
node "M3.42"
feature "Pattern of M3.26:36"
node "M3.43"
feature "Pattern of M3.25:37"
node "M3.44"
feature "Pattern of M3.25:38"
node "M3.45"
feature "Pattern of M3.25:39"
node "M3.46"
feature "Pattern of M3.25:40"
node "M3.47"
feature "Pattern of M3.25:41"
node "M3.48"
feature "Pattern of M3.25:42"
node "M3.49"
feature "Pattern of M3.25:43"
node "M3.50"
feature "Pattern of M3.25:44"
node "M3.51"
feature "Pattern of M3.25:45"
node "M3.52"
feature "Pattern of M3.25:46"
node "M3.53"
feature "Pattern of M3.25:47"
node "M3.54"
feature "Pattern of M3.25:48"
node "M3.55"
feature "Pattern of M3.25:49"
node "M3.56"
feature "Pattern of M3.25:50"
node "M3.57"
feature "Pattern of M3.25:51"
node "M3.58"
feature "Pattern of M3.25:52"
node "M3.59"
feature "Pattern of M3.25:53"
node "M3.60"
node "M3.61"
node "M3.62"
node "M3.63"
node "M3.64"
node "M3.65"
node "M3.66"
node "M3.67"
node "M3.68"
node "M3.69"
node "M3.70"
node "M3.71"
node "M3.72"
node "M3.73"
node "M3.74"
node "M3.75"
node "M3.76"
node "M3.77"
node "M3.78"
node "M3.79"
node "M3.80"
node "M3.81"
node "M3.82"
node "M3.83"
node "M3.84"
node "M3.85"
node "M3.86"
node "M3.87"
node "M3.88"
node "M3.89"
node "M3.90"
node "M3.91"
node "M3.92"
node "M3.93"
node "M3.94"
node "M3.95"
node "M3.96"
node "M3.97"
node "M3.98"
node "M3.99"
node "M3.100"
node "M3.101"
node "M3.102"
node "M3.103"
node "M3.104"
node "M3.105"
node "M3.106"
node "M3.107"
node "M3.121"
node "M3.122"
node "M3.123"
node "M3.124"
node "M3.125"
node "M3.126"
node "M3.127"
node "M3.128"
node "M3.129"
node "M3.130"
node "M3.131"
node "M3.132"
node "M3.133"
node "M3.134"
node "M3.135"
node "M3.136"
node "M3.137"
node "M3.138"
node "M3.139"
node "M3.140"
node "M3.141"
node "M3.142"
node "M3.143"
node "M3.144"
node "M3.145"
node "M3.146"
node "M3.147"
node "M3.148"
node "M3.149"
node "M3.150"
node "M3.151"
node "M3.152"
node "M3.153"
node "M3.154"
node "M3.155"
node "M3.156"
node "M3.157"
node "M3.158"
node "M3.159"
node "M3.160"
node "M3.161"
node "M3.162"
node "M3.163"
node "M3.164"
node "M3.165"
node "M3.166"
node "M3.167"
node "M3.168"
node "M3.169"
node "M3.170"
node "M3.171"
node "M3.172"
node "M3.173"
node "M3.174"
node "M3.175"
node "M3.176"
node "M3.177"
node "M3.178"
node "M3.179"
node "M3.180"
node "M3.181"
node "M3.182"
node "M3.183"
node "M3.184"
node "M3.185"
node "M3.186"
node "M3.187"
node "M3.188"
node "M3.189"
node "M3.190"
node "M3.191"
node "M3.192"
node "M3.193"
node "M3.194"
node "M3.195"
node "M3.196"
node "M3.197"
node "M3.198"
node "M3.199"
node "M3.200"
node "M3.201"
node "M3.207"
feature "Pattern of M3.207:59"
node "M3.208"
node "M3.209"
feature "Pattern of M3.209:60"
node "M3.210"
node "M3.211"
node "M3.212"
feature "Pattern of M3.212:61"
node "M3.213"
node "M3.214"
node "M3.215"
feature "Pattern of M3.215:62"
node "M3.216"
feature "Pattern of M3.214:63"
node "M3.217"
feature "Pattern of M3.214:64"
node "M3.218"
node "M3.219"
node "Cimento"
node "Projected Loop1"
node "Projected Loop2"
node "Projected Loop3"
node "Projected Loop4"
node "Projected Loop5"
node "Projected Loop6"
other parameters: "TIJOLO_PADRAO_LARG" = 115, "TIJOLO_PADRAO_PROF" = 58, "AMAR_PADRAO_LARG" = 115, "AMAR_PADRAO_PROF" = 58
